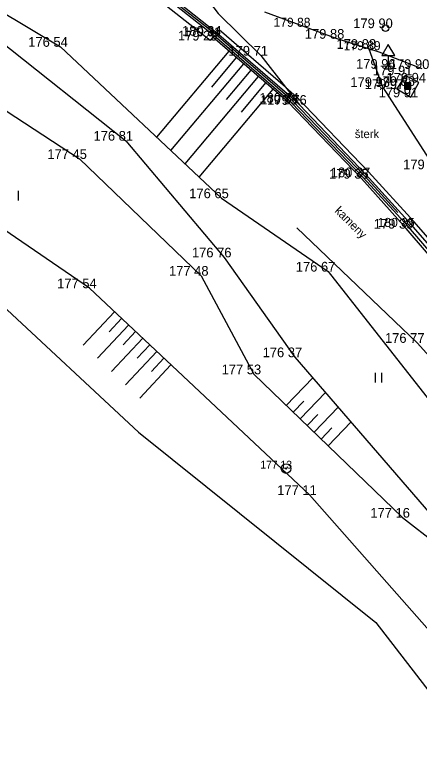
# Model space of a CAD drawing. Extents: x -537755 to -537431, y -1180722 to -1180510.
# Drawn here: x -537671.4 to -537640, y -1180623.4 to -1180566.9 of the extents above; entities that cross this region are included whole.
import ezdxf

# ---------------------------------------------------------------- set-up
doc = ezdxf.new("R2010")
doc.units = 0
for name, color, linetype in [('Vrstva 1', 7, 'Continuous'), ('Vrstva 10', 7, 'Continuous'), ('Vrstva 11', 7, 'Continuous'), ('Vrstva 14', 7, 'Continuous'), ('Vrstva 15', 7, 'Continuous'), ('Vrstva 21', 7, 'Continuous'), ('Vrstva 22', 7, 'Continuous'), ('Vrstva 25', 7, 'Continuous'), ('Vrstva 28', 7, 'Continuous'), ('Vrstva 3', 7, 'Continuous'), ('Vrstva 34', 7, 'Continuous'), ('Vrstva 36', 7, 'Continuous'), ('Vrstva 40', 7, 'Continuous'), ('Vrstva 7', 7, 'Continuous'), ('Vrstva 9', 7, 'Continuous')]:
    doc.layers.add(name, color=color, linetype=linetype)

msp = doc.modelspace()

# ---------------------------------------------------------------- linework, layer by layer
at = {"layer": 'Vrstva 1'}
for p, q in [((-537649.021, -1180567.803), (-537649.021, -1180567.803)), ((-537642.677, -1180567.908), (-537642.677, -1180567.908)), ((-537655.984, -1180568.546), (-537655.984, -1180568.546)), ((-537655.96, -1180568.45), (-537655.96, -1180568.45)), ((-537655.956, -1180568.491), (-537655.956, -1180568.491)), ((-537656.266, -1180568.863), (-537656.266, -1180568.863)), ((-537646.433, -1180568.727), (-537646.433, -1180568.727)), ((-537667.87, -1180569.35), (-537667.87, -1180569.35)), ((-537643.97, -1180569.51), (-537643.97, -1180569.51)), ((-537643.586, -1180569.617), (-537643.586, -1180569.617)), ((-537652.35, -1180570.03), (-537652.35, -1180570.03)), ((-537642.46, -1180571.05), (-537642.46, -1180571.05)), ((-537641.16, -1180571.56), (-537641.16, -1180571.56)), ((-537642.9, -1180572.46), (-537642.9, -1180572.46)), ((-537641.79, -1180572.61), (-537641.79, -1180572.61)), ((-537640.96, -1180572.38), (-537640.96, -1180572.38)), ((-537640.1, -1180572.12), (-537640.1, -1180572.12)), ((-537649.952, -1180573.678), (-537649.952, -1180573.678)), ((-537649.84, -1180573.62), (-537649.84, -1180573.62)), ((-537640.71, -1180573.26), (-537640.71, -1180573.26)), ((-537650.032, -1180573.803), (-537650.032, -1180573.803)), ((-537649.35, -1180573.84), (-537649.35, -1180573.84)), ((-537662.81, -1180576.62), (-537662.81, -1180576.62)), ((-537666.39, -1180578.03), (-537666.39, -1180578.03)), ((-537644.4, -1180579.39), (-537644.4, -1180579.39)), ((-537644.548, -1180579.555), (-537644.548, -1180579.555)), ((-537644.42, -1180579.447), (-537644.42, -1180579.447)), ((-537655.39, -1180581.07), (-537655.39, -1180581.07)), ((-537640.95, -1180583.298), (-537640.95, -1180583.298)), ((-537640.93, -1180583.24), (-537640.93, -1180583.24)), ((-537641.085, -1180583.425), (-537641.085, -1180583.425)), ((-537655.18, -1180585.65), (-537655.18, -1180585.65)), ((-537647.13, -1180586.75), (-537647.13, -1180586.75)), ((-537656.96, -1180587.07), (-537656.96, -1180587.07)), ((-537665.63, -1180588.04), (-537665.63, -1180588.04)), ((-537640.217, -1180592.267), (-537640.217, -1180592.267)), ((-537649.7, -1180593.38), (-537649.7, -1180593.38)), ((-537652.88, -1180594.7), (-537652.88, -1180594.7)), ((-537648.57, -1180604.04), (-537648.57, -1180604.04)), ((-537641.35, -1180605.8), (-537641.35, -1180605.8))]:
    msp.add_line(p, q, dxfattribs=at)
at = {"layer": 'Vrstva 10'}
msp.add_line((-537646.433, -1180568.727), (-537652.04, -1180566.674), dxfattribs=at)
for points in [[(-537643.97, -1180569.51), (-537646.433, -1180568.727)], [(-537639.843, -1180571.064), (-537643.166, -1180569.763), (-537643.97, -1180569.51)]]:
    msp.add_lwpolyline(points, dxfattribs=at)
at = {"layer": 'Vrstva 11'}
for p, q in [((-537655.574, -1180568.029), (-537655.765, -1180568.26)), ((-537643.97, -1180569.51), (-537642.9, -1180572.46)), ((-537642.9, -1180572.46), (-537638.81, -1180578.83)), ((-537643.982, -1180579.037), (-537649.538, -1180573.242)), ((-537640.452, -1180582.898), (-537643.982, -1180579.037)), ((-537637.167, -1180586.683), (-537640.452, -1180582.898))]:
    msp.add_line(p, q, dxfattribs=at)
for points in [[(-537657.77, -1180563.99), (-537655.65, -1180566.78), (-537652.35, -1180570.03)], [(-537649.538, -1180573.242), (-537650.422, -1180572.478), (-537655.574, -1180568.029)], [(-537652.35, -1180570.03), (-537650.422, -1180572.478), (-537649.35, -1180573.84)]]:
    msp.add_lwpolyline(points, dxfattribs=at)
at = {"layer": 'Vrstva 14'}
for p, q in [((-537683.94, -1180559.8), (-537667.87, -1180569.35)), ((-537687.94, -1180563.99), (-537666.39, -1180578.03)), ((-537673.31, -1180568.31), (-537662.81, -1180576.62)), ((-537667.87, -1180569.35), (-537655.39, -1180581.07)), ((-537665.63, -1180588.04), (-537683.35, -1180575.9)), ((-537662.81, -1180576.62), (-537655.18, -1180585.65)), ((-537666.39, -1180578.03), (-537656.96, -1180587.07)), ((-537655.39, -1180581.07), (-537647.13, -1180586.75)), ((-537679.05, -1180583.16), (-537661.82, -1180599.18)), ((-537649.56, -1180583.36), (-537640.217, -1180592.267)), ((-537655.18, -1180585.65), (-537649.7, -1180593.38)), ((-537647.13, -1180586.75), (-537637.42, -1180599.09)), ((-537656.96, -1180587.07), (-537652.88, -1180594.7)), ((-537648.57, -1180604.04), (-537665.63, -1180588.04)), ((-537649.7, -1180593.38), (-537634.19, -1180611.33)), ((-537652.88, -1180594.7), (-537641.35, -1180605.8)), ((-537661.82, -1180599.18), (-537643.43, -1180613.91)), ((-537636.81, -1180617.37), (-537648.57, -1180604.04)), ((-537641.35, -1180605.8), (-537634.19, -1180611.33)), ((-537643.43, -1180613.91), (-537633.13, -1180627.24))]:
    msp.add_line(p, q, dxfattribs=at)
msp.add_lwpolyline([(-537640.217, -1180592.267), (-537638.065, -1180594.648), (-537635.972, -1180597.083), (-537633.941, -1180599.569)], dxfattribs=at)
at = {"layer": 'Vrstva 15'}
for p, q in [((-537660.407, -1180576.359), (-537654.782, -1180569.699)), ((-537656.141, -1180572.47), (-537654.214, -1180570.189)), ((-537659.312, -1180577.387), (-537653.647, -1180570.68)), ((-537654.995, -1180573.438), (-537653.079, -1180571.17)), ((-537658.217, -1180578.415), (-537652.512, -1180571.661)), ((-537653.848, -1180574.406), (-537651.944, -1180572.151)), ((-537657.122, -1180579.444), (-537651.377, -1180572.642)), ((-537666.104, -1180592.44), (-537663.686, -1180589.862)), ((-537664.106, -1180591.406), (-537663.139, -1180590.375)), ((-537665.01, -1180593.466), (-537662.592, -1180590.888)), ((-537663.012, -1180592.433), (-537662.045, -1180591.402)), ((-537663.916, -1180594.493), (-537661.498, -1180591.915)), ((-537662.822, -1180595.519), (-537660.404, -1180592.941)), ((-537661.918, -1180593.459), (-537660.951, -1180592.428)), ((-537660.824, -1180594.485), (-537659.857, -1180593.454)), ((-537661.728, -1180596.545), (-537659.31, -1180593.967)), ((-537648.319, -1180594.978), (-537650.374, -1180597.113)), ((-537647.334, -1180596.118), (-537649.293, -1180598.153)), ((-537649.006, -1180596.773), (-537649.834, -1180597.633)), ((-537646.349, -1180597.258), (-537648.213, -1180599.194)), ((-537647.925, -1180597.813), (-537648.753, -1180598.673)), ((-537645.364, -1180598.398), (-537647.132, -1180600.234)), ((-537646.844, -1180598.854), (-537647.672, -1180599.714))]:
    msp.add_line(p, q, dxfattribs=at)
at = {"layer": 'Vrstva 21'}
for radius in [0.375, 0.05]:
    msp.add_circle((-537650.378, -1180601.996), radius, dxfattribs=at)
at = {"layer": 'Vrstva 25'}
for points in [[(-537641.21, -1180572.63), (-537640.71, -1180572.63), (-537640.71, -1180572.13), (-537641.21, -1180572.13)], [(-537641.16, -1180572.58), (-537640.76, -1180572.58), (-537640.76, -1180572.18), (-537641.16, -1180572.18)], [(-537641.11, -1180572.53), (-537640.81, -1180572.53), (-537640.81, -1180572.23), (-537641.11, -1180572.23)], [(-537641.06, -1180572.48), (-537640.86, -1180572.48), (-537640.86, -1180572.28), (-537641.06, -1180572.28)], [(-537641.01, -1180572.43), (-537640.91, -1180572.43), (-537640.91, -1180572.33), (-537641.01, -1180572.33)]]:
    msp.add_lwpolyline(points, close=True, dxfattribs=at)
at = {"layer": 'Vrstva 28'}
msp.add_circle((-537642.677, -1180567.908), 0.25, dxfattribs=at)
at = {"layer": 'Vrstva 34'}
for p, q in [((-537642.46, -1180570.034), (-537642.46, -1180571.05)), ((-537642.71, -1180571.05), (-537642.21, -1180571.05))]:
    msp.add_line(p, q, dxfattribs=at)
msp.add_lwpolyline([(-537642.96, -1180570.034), (-537641.96, -1180570.034), (-537642.46, -1180569.166)], close=True, dxfattribs=at)
at = {"layer": 'Vrstva 36'}
for p, q in [((-537671.116, -1180581.255), (-537671.116, -1180580.505)), ((-537643.449, -1180595.343), (-537643.449, -1180594.593)), ((-537642.949, -1180595.343), (-537642.949, -1180594.593))]:
    msp.add_line(p, q, dxfattribs=at)
at = {"layer": 'Vrstva 7'}
for p, q in [((-537655.956, -1180568.491), (-537662.25, -1180563.533)), ((-537655.765, -1180568.26), (-537662.078, -1180563.287)), ((-537656.266, -1180568.863), (-537662.438, -1180564.001)), ((-537656.062, -1180568.593), (-537656.266, -1180568.863)), ((-537650.212, -1180573.648), (-537656.062, -1180568.593)), ((-537649.952, -1180573.678), (-537655.956, -1180568.491)), ((-537649.745, -1180573.46), (-537655.765, -1180568.26)), ((-537644.548, -1180579.555), (-537650.212, -1180573.648)), ((-537644.42, -1180579.447), (-537649.952, -1180573.678)), ((-537640.676, -1180583.098), (-537644.201, -1180579.242)), ((-537641.085, -1180583.425), (-537644.548, -1180579.555)), ((-537640.9, -1180583.298), (-537644.42, -1180579.447))]:
    msp.add_line(p, q, dxfattribs=at)
for points in [[(-537640.1, -1180572.12), (-537641.16, -1180571.56), (-537641.79, -1180572.61), (-537640.71, -1180573.26), (-537640.1, -1180572.12)], [(-537649.35, -1180573.84), (-537649.745, -1180573.46)], [(-537644.201, -1180579.242), (-537649.35, -1180573.84)], [(-537636.355, -1180588.346), (-537636.45, -1180588.405), (-537636.81, -1180588.529), (-537637.707, -1180586.976), (-537640.9, -1180583.298)], [(-537636.49, -1180588.09), (-537636.674, -1180588.165), (-537637.462, -1180586.801), (-537640.676, -1180583.098)], [(-537636.381, -1180588.493), (-537636.961, -1180588.726), (-537637.912, -1180587.08), (-537641.085, -1180583.425)]]:
    msp.add_lwpolyline(points, dxfattribs=at)
at = {"layer": 'Vrstva 9'}
for p, q in [((-537655.861, -1180568.375), (-537662.164, -1180563.41)), ((-537649.849, -1180573.569), (-537655.861, -1180568.375)), ((-537644.31, -1180579.344), (-537649.849, -1180573.569)), ((-537641.721, -1180582.178), (-537644.31, -1180579.344))]:
    msp.add_line(p, q, dxfattribs=at)

# ---------------------------------------------------------------- texts
at = {"layer": 'Vrstva 22'}
msp.add_text('177 13 ', height=0.6, dxfattribs=at).set_placement((-537652.378, -1180601.996))
at = {"layer": 'Vrstva 3'}
for s, height, p in [('179 88 ', 0.7, (-537651.354, -1180567.803)), ('179 90 ', 0.75, (-537645.177, -1180567.908)), ('179 29 ', 0.75, (-537658.766, -1180568.863)), ('180 34 ', 0.75, (-537658.456, -1180568.491)), ('179 31 ', 0.7, (-537658.317, -1180568.546)), ('179 88 ', 0.75, (-537648.933, -1180568.727)), ('176 54 ', 0.75, (-537670.37, -1180569.35)), ('179 88 ', 0.75, (-537646.47, -1180569.51)), ('179 89 ', 0.7, (-537645.919, -1180569.617)), ('179 71 ', 0.75, (-537654.85, -1180570.03)), ('179 96 ', 0.75, (-537644.96, -1180571.05)), ('179 90 ', 0.75, (-537642.343, -1180571.064)), ('179 91 ', 0.75, (-537643.66, -1180571.56)), ('179 94 ', 0.75, (-537642.6, -1180572.12)), ('179 93 ', 0.75, (-537645.4, -1180572.46)), ('179 97 ', 0.75, (-537644.29, -1180572.61)), ('179 88 ', 0.75, (-537643.46, -1180572.38)), ('179 91 ', 0.75, (-537643.21, -1180573.26)), ('180 34 ', 0.75, (-537652.452, -1180573.678)), ('179 33 ', 0.7, (-537652.365, -1180573.803)), ('179 76 ', 0.75, (-537651.85, -1180573.84)), ('176 81 ', 0.75, (-537665.31, -1180576.62)), ('177 45 ', 0.75, (-537668.89, -1180578.03)), ('179 89 ', 0.75, (-537641.31, -1180578.83)), ('179 35 ', 0.75, (-537647.048, -1180579.555)), ('180 37 ', 0.75, (-537646.92, -1180579.447)), ('176 65 ', 0.75, (-537657.89, -1180581.07)), ('179 39 ', 0.75, (-537643.585, -1180583.425)), ('180 35 ', 0.7, (-537643.283, -1180583.298)), ('176 76 ', 0.75, (-537657.68, -1180585.65)), ('176 67 ', 0.75, (-537649.63, -1180586.75)), ('177 48 ', 0.75, (-537659.46, -1180587.07)), ('177 54 ', 0.75, (-537668.13, -1180588.04)), ('176 77 ', 0.75, (-537642.717, -1180592.267)), ('176 37 ', 0.75, (-537652.2, -1180593.38)), ('177 53 ', 0.75, (-537655.38, -1180594.7)), ('177 11 ', 0.75, (-537651.07, -1180604.04)), ('177 16 ', 0.75, (-537643.85, -1180605.8))]:
    msp.add_text(s, height=height, dxfattribs=at).set_placement(p)
at = {"layer": 'Vrstva 40'}
msp.add_text('šterk', height=0.65, dxfattribs=at).set_placement((-537645.056, -1180576.417))
msp.add_text('kameny', height=0.65, rotation=315.1833, dxfattribs=at).set_placement((-537646.659, -1180582.1))

doc.saveas('drawing.dxf')
